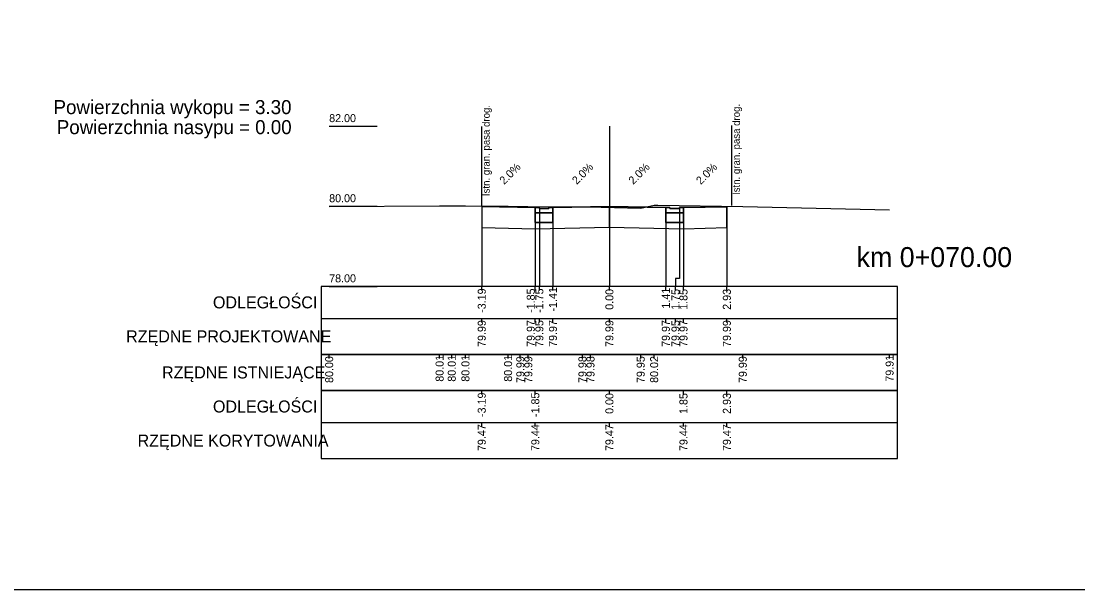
# Model space of a CAD drawing. Extents: x 7492871 to 7493499, y 5802964 to 5802992.
# Drawn here: x 7492903.18 to 7492929.58, y 5802963.88 to 5802978.08 of the extents above; entities that cross this region are included whole.
import ezdxf

# ---------------------------------------------------------------- set-up
doc = ezdxf.new("R2010")
doc.units = 0
for name, color, linetype in [('_wydruk', 7, 'Continuous'), ('d_pop_nasyp_opis', 7, 'Continuous'), ('d_pop_wykop_opis', 7, 'Continuous'), ('opisy_ramki_pop', 7, 'Continuous'), ('pop_comp_kostka', 7, 'Continuous'), ('pop_comp_lawa', 7, 'Continuous'), ('pop_comp_scieralna', 7, 'Continuous'), ('pop_granica_istn', 7, 'Continuous'), ('pop_opis', 7, 'Continuous'), ('pop_os', 7, 'Continuous'), ('pop_pikietaz', 7, 'Continuous'), ('pop_teren', 7, 'Continuous')]:
    doc.layers.add(name, color=color, linetype=linetype)

msp = doc.modelspace()

# ---------------------------------------------------------------- linework, layer by layer
msp.add_lwpolyline([(7492914.685, 5802973.452), (7492916.023, 5802973.425), (7492916.123, 5802973.425), (7492916.124, 5802973.405), (7492916.363, 5802973.405), (7492916.364, 5802973.425), (7492916.464, 5802973.425), (7492917.874, 5802973.453), (7492919.284, 5802973.425), (7492919.384, 5802973.425), (7492919.385, 5802973.405), (7492919.624, 5802973.405), (7492919.625, 5802973.425), (7492919.725, 5802973.425), (7492920.808, 5802973.447)])
at = {"layer": '_wydruk'}
msp.add_lwpolyline([(7492871.369, 5802992.281), (7493499.283, 5802992.281), (7493499.283, 5802963.881), (7492871.369, 5802963.881)], close=True, dxfattribs=at)
at = {"layer": 'opisy_ramki_pop'}
for points in [[(7492914.685, 5802972.932), (7492914.685, 5802971.659), (7492914.685, 5802971.659), (7492914.685, 5802971.459)], [(7492916.023, 5802972.896), (7492916.023, 5802971.659), (7492916.023, 5802971.659), (7492916.023, 5802971.459)], [(7492917.874, 5802972.933), (7492917.874, 5802971.659), (7492917.874, 5802971.659), (7492917.874, 5802971.459)], [(7492919.725, 5802972.896), (7492919.725, 5802971.659), (7492919.725, 5802971.659), (7492919.725, 5802971.459)], [(7492920.808, 5802972.927), (7492920.808, 5802971.659), (7492920.808, 5802971.659), (7492920.808, 5802971.459)]]:
    msp.add_lwpolyline(points, dxfattribs=at)
at = {"layer": 'pop_comp_kostka'}
for p, q in [((7492916.123, 5802973.425), (7492916.023, 5802973.425)), ((7492916.023, 5802973.425), (7492916.023, 5802973.295)), ((7492916.124, 5802973.405), (7492916.123, 5802973.425)), ((7492916.363, 5802973.405), (7492916.124, 5802973.405)), ((7492916.364, 5802973.425), (7492916.363, 5802973.405)), ((7492916.464, 5802973.425), (7492916.364, 5802973.425)), ((7492916.464, 5802973.295), (7492916.464, 5802973.425)), ((7492919.384, 5802973.425), (7492919.284, 5802973.425)), ((7492919.284, 5802973.425), (7492919.284, 5802973.295)), ((7492919.385, 5802973.405), (7492919.384, 5802973.425)), ((7492919.624, 5802973.405), (7492919.385, 5802973.405)), ((7492919.625, 5802973.425), (7492919.624, 5802973.405)), ((7492919.725, 5802973.425), (7492919.625, 5802973.425)), ((7492919.725, 5802973.295), (7492919.725, 5802973.425)), ((7492916.023, 5802973.295), (7492916.464, 5802973.295)), ((7492919.284, 5802973.295), (7492919.725, 5802973.295))]:
    msp.add_line(p, q, dxfattribs=at)
at = {"layer": 'pop_comp_lawa'}
for p, q in [((7492916.464, 5802973.295), (7492916.023, 5802973.295)), ((7492916.023, 5802973.295), (7492916.023, 5802973.055)), ((7492916.464, 5802973.055), (7492916.464, 5802973.295)), ((7492919.725, 5802973.295), (7492919.284, 5802973.295)), ((7492919.284, 5802973.295), (7492919.284, 5802973.055)), ((7492919.725, 5802973.055), (7492919.725, 5802973.295)), ((7492916.023, 5802973.055), (7492916.464, 5802973.055)), ((7492919.284, 5802973.055), (7492919.725, 5802973.055))]:
    msp.add_line(p, q, dxfattribs=at)
at = {"layer": 'pop_comp_scieralna'}
for p, q in [((7492916.023, 5802973.425), (7492914.685, 5802973.452)), ((7492914.685, 5802973.452), (7492914.685, 5802972.932)), ((7492916.023, 5802973.055), (7492916.023, 5802973.425)), ((7492917.874, 5802973.453), (7492916.464, 5802973.425)), ((7492916.464, 5802973.425), (7492916.464, 5802973.055)), ((7492917.874, 5802972.933), (7492917.874, 5802973.453)), ((7492919.284, 5802973.425), (7492917.874, 5802973.453)), ((7492917.874, 5802973.453), (7492917.874, 5802972.933)), ((7492919.284, 5802973.055), (7492919.284, 5802973.425)), ((7492920.808, 5802973.447), (7492919.725, 5802973.425)), ((7492919.725, 5802973.425), (7492919.725, 5802973.055)), ((7492920.808, 5802972.927), (7492920.808, 5802973.447)), ((7492914.685, 5802972.932), (7492916.023, 5802972.896)), ((7492916.464, 5802973.055), (7492916.023, 5802973.055)), ((7492916.023, 5802972.896), (7492917.874, 5802972.933)), ((7492917.874, 5802972.933), (7492919.725, 5802972.896)), ((7492919.725, 5802973.055), (7492919.284, 5802973.055)), ((7492919.725, 5802972.896), (7492920.808, 5802972.927))]:
    msp.add_line(p, q, dxfattribs=at)
at = {"layer": 'pop_granica_istn'}
for p, q in [((7492920.934, 5802973.979), (7492920.934, 5802975.479)), ((7492914.685, 5802973.952), (7492914.685, 5802975.452)), ((7492914.685, 5802973.452), (7492914.685, 5802973.952)), ((7492920.934, 5802973.479), (7492920.934, 5802973.979))]:
    msp.add_line(p, q, dxfattribs=at)
at = {"layer": 'pop_opis'}
for p, q in [((7492910.874, 5802975.459), (7492912.074, 5802975.459)), ((7492910.874, 5802973.459), (7492912.074, 5802973.459)), ((7492910.674, 5802971.459), (7492910.674, 5802969.759)), ((7492910.674, 5802971.459), (7492910.674, 5802969.759)), ((7492910.674, 5802971.459), (7492910.674, 5802969.759)), ((7492910.674, 5802971.459), (7492910.674, 5802969.759)), ((7492910.874, 5802971.459), (7492912.074, 5802971.459)), ((7492914.685, 5802971.359), (7492914.685, 5802971.459)), ((7492916.023, 5802971.359), (7492916.023, 5802971.459)), ((7492916.124, 5802971.359), (7492916.124, 5802971.459)), ((7492916.464, 5802971.359), (7492916.464, 5802971.459)), ((7492917.874, 5802971.359), (7492917.874, 5802971.459)), ((7492919.284, 5802971.359), (7492919.284, 5802971.459)), ((7492919.525, 5802971.359), (7492919.525, 5802971.459)), ((7492919.725, 5802971.359), (7492919.725, 5802971.459)), ((7492920.808, 5802971.359), (7492920.808, 5802971.459)), ((7492910.674, 5802970.659), (7492925.074, 5802970.659)), ((7492910.674, 5802970.659), (7492925.074, 5802970.659)), ((7492910.674, 5802970.659), (7492925.074, 5802970.659)), ((7492910.674, 5802970.659), (7492925.074, 5802970.659)), ((7492914.685, 5802970.559), (7492914.685, 5802970.659)), ((7492916.023, 5802970.559), (7492916.023, 5802970.659)), ((7492916.124, 5802970.559), (7492916.124, 5802970.659)), ((7492916.464, 5802970.559), (7492916.464, 5802970.659)), ((7492917.874, 5802970.559), (7492917.874, 5802970.659)), ((7492919.284, 5802970.559), (7492919.284, 5802970.659)), ((7492919.525, 5802970.559), (7492919.525, 5802970.659)), ((7492919.725, 5802970.559), (7492919.725, 5802970.659)), ((7492920.808, 5802970.559), (7492920.808, 5802970.659)), ((7492910.674, 5802969.759), (7492910.674, 5802968.859)), ((7492910.874, 5802969.659), (7492910.874, 5802969.759)), ((7492913.632, 5802969.659), (7492913.632, 5802969.759)), ((7492913.936, 5802969.659), (7492913.936, 5802969.759)), ((7492914.278, 5802969.659), (7492914.278, 5802969.759)), ((7492915.343, 5802969.659), (7492915.343, 5802969.759)), ((7492915.649, 5802969.659), (7492915.649, 5802969.759)), ((7492915.849, 5802969.659), (7492915.849, 5802969.759)), ((7492917.202, 5802969.659), (7492917.202, 5802969.759)), ((7492917.402, 5802969.659), (7492917.402, 5802969.759)), ((7492918.656, 5802969.659), (7492918.656, 5802969.759)), ((7492918.992, 5802969.659), (7492918.992, 5802969.759)), ((7492921.206, 5802969.659), (7492921.206, 5802969.759)), ((7492924.874, 5802969.659), (7492924.874, 5802969.759)), ((7492910.674, 5802968.859), (7492910.674, 5802967.159)), ((7492914.685, 5802968.759), (7492914.685, 5802968.859)), ((7492916.023, 5802968.759), (7492916.023, 5802968.859)), ((7492917.874, 5802968.759), (7492917.874, 5802968.859)), ((7492919.725, 5802968.759), (7492919.725, 5802968.859)), ((7492920.808, 5802968.759), (7492920.808, 5802968.859)), ((7492910.674, 5802968.059), (7492925.074, 5802968.059)), ((7492914.685, 5802967.959), (7492914.685, 5802968.059)), ((7492916.023, 5802967.959), (7492916.023, 5802968.059)), ((7492917.874, 5802967.959), (7492917.874, 5802968.059)), ((7492919.725, 5802967.959), (7492919.725, 5802968.059)), ((7492920.808, 5802967.959), (7492920.808, 5802968.059))]:
    msp.add_line(p, q, dxfattribs=at)
for points in [[(7492914.685, 5802973.452), (7492914.685, 5802971.659), (7492914.685, 5802971.659), (7492914.685, 5802971.459)], [(7492916.023, 5802973.425), (7492916.023, 5802971.659), (7492916.023, 5802971.659), (7492916.023, 5802971.459)], [(7492916.124, 5802973.405), (7492916.124, 5802971.659), (7492916.124, 5802971.659), (7492916.124, 5802971.459)], [(7492916.464, 5802973.425), (7492916.464, 5802971.659), (7492916.464, 5802971.659), (7492916.464, 5802971.459)], [(7492917.874, 5802973.453), (7492917.874, 5802971.659), (7492917.874, 5802971.659), (7492917.874, 5802971.459)], [(7492919.284, 5802973.425), (7492919.284, 5802971.659), (7492919.284, 5802971.659), (7492919.284, 5802971.459)], [(7492919.624, 5802973.405), (7492919.624, 5802971.659), (7492919.525, 5802971.659), (7492919.525, 5802971.459)], [(7492919.725, 5802973.425), (7492919.725, 5802971.659), (7492919.725, 5802971.659), (7492919.725, 5802971.459)], [(7492920.808, 5802973.447), (7492920.808, 5802971.659), (7492920.808, 5802971.659), (7492920.808, 5802971.459)]]:
    msp.add_lwpolyline(points, dxfattribs=at)
for points in [[(7492910.674, 5802971.459), (7492910.674, 5802969.759), (7492925.074, 5802969.759), (7492925.074, 5802971.459)], [(7492910.674, 5802971.459), (7492910.674, 5802969.759), (7492925.074, 5802969.759), (7492925.074, 5802971.459)], [(7492910.674, 5802971.459), (7492910.674, 5802969.759), (7492925.074, 5802969.759), (7492925.074, 5802971.459)], [(7492910.674, 5802971.459), (7492910.674, 5802969.759), (7492925.074, 5802969.759), (7492925.074, 5802971.459)], [(7492910.674, 5802969.759), (7492910.674, 5802968.859), (7492925.074, 5802968.859), (7492925.074, 5802969.759)], [(7492910.674, 5802968.859), (7492910.674, 5802967.159), (7492925.074, 5802967.159), (7492925.074, 5802968.859)]]:
    msp.add_lwpolyline(points, close=True, dxfattribs=at)
at = {"layer": 'pop_os'}
msp.add_line((7492917.874, 5802975.459), (7492917.874, 5802971.459), dxfattribs=at)
at = {"layer": 'pop_teren'}
msp.add_lwpolyline([(7492910.874, 5802973.455), (7492913.632, 5802973.472), (7492913.936, 5802973.473), (7492914.278, 5802973.467), (7492915.343, 5802973.465), (7492915.649, 5802973.449), (7492915.84, 5802973.454), (7492917.202, 5802973.443), (7492917.332, 5802973.444), (7492918.656, 5802973.412), (7492918.992, 5802973.483), (7492919.085, 5802973.485), (7492921.206, 5802973.451), (7492924.874, 5802973.371)], dxfattribs=at)

# ---------------------------------------------------------------- texts
at = {"layer": 'd_pop_nasyp_opis'}
msp.add_text('Powierzchnia nasypu = 0.00', height=0.35, dxfattribs=at).set_placement((7492904.069, 5802975.259))
at = {"layer": 'd_pop_wykop_opis'}
msp.add_text('Powierzchnia wykopu = 3.30', height=0.35, dxfattribs=at).set_placement((7492903.988, 5802975.759))
at = {"layer": 'pop_granica_istn'}
for p in [(7492921.133, 5802973.74), (7492914.884, 5802973.713)]:
    msp.add_text('Istn. gran. pasa drog.', height=0.18, rotation=90, dxfattribs=at).set_placement(p)
at = {"layer": 'pop_opis'}
for s, height, p in [('82.00', 0.2, (7492910.874, 5802975.559)), ('80.00', 0.2, (7492910.874, 5802973.559)), ('78.00', 0.2, (7492910.874, 5802971.559)), ('ODLEGŁOŚCI', 0.3, (7492907.97, 5802970.909)), ('ODLEGŁOŚCI', 0.3, (7492907.97, 5802970.909)), ('ODLEGŁOŚCI', 0.3, (7492907.97, 5802970.909)), ('ODLEGŁOŚCI', 0.3, (7492907.97, 5802970.909)), ('RZĘDNE PROJEKTOWANE', 0.3, (7492905.802, 5802970.059)), ('RZĘDNE PROJEKTOWANE', 0.3, (7492905.802, 5802970.059)), ('RZĘDNE PROJEKTOWANE', 0.3, (7492905.802, 5802970.059)), ('RZĘDNE PROJEKTOWANE', 0.3, (7492905.802, 5802970.059)), ('RZĘDNE ISTNIEJĄCE', 0.3, (7492906.699, 5802969.159)), ('ODLEGŁOŚCI', 0.3, (7492907.97, 5802968.309)), ('RZĘDNE KORYTOWANIA', 0.3, (7492906.088, 5802967.459))]:
    msp.add_text(s, height=height, dxfattribs=at).set_placement(p)
for s, rotation, p in [('2.0%', 45, (7492915.246, 5802973.988)), ('2.0%', 45, (7492917.06, 5802973.989)), ('2.0%', 45, (7492918.47, 5802973.989)), ('2.0%', 45, (7492920.158, 5802973.986)), ('-3.19', 90, (7492914.785, 5802970.797)), ('-1.85', 90, (7492916.01, 5802970.796)), ('-1.75', 90, (7492916.224, 5802970.796)), ('-1.41', 90, (7492916.564, 5802970.829)), ('0.00', 90, (7492917.974, 5802970.874)), ('1.41', 90, (7492919.384, 5802970.905)), ('1.75', 90, (7492919.625, 5802970.873)), ('1.85', 90, (7492919.825, 5802970.873)), ('2.93', 90, (7492920.908, 5802970.874)), ('79.99', 90, (7492914.785, 5802969.946)), ('79.97', 90, (7492916.01, 5802969.947)), ('79.95', 90, (7492916.224, 5802969.945)), ('79.97', 90, (7492916.564, 5802969.947)), ('79.99', 90, (7492917.974, 5802969.946)), ('79.97', 90, (7492919.384, 5802969.947)), ('79.95', 90, (7492919.625, 5802969.945)), ('79.97', 90, (7492919.825, 5802969.947)), ('79.99', 90, (7492920.908, 5802969.946)), ('80.00', 90, (7492910.974, 5802969.047)), ('80.01', 90, (7492913.732, 5802969.078)), ('80.01', 90, (7492914.036, 5802969.078)), ('80.01', 90, (7492914.378, 5802969.078)), ('80.01', 90, (7492915.443, 5802969.078)), ('79.99', 90, (7492915.749, 5802969.046)), ('79.99', 90, (7492915.949, 5802969.046)), ('79.98', 90, (7492917.302, 5802969.046)), ('79.98', 90, (7492917.502, 5802969.046)), ('79.95', 90, (7492918.756, 5802969.045)), ('80.02', 90, (7492919.092, 5802969.048)), ('79.99', 90, (7492921.306, 5802969.046)), ('79.91', 90, (7492924.974, 5802969.078)), ('-3.19', 90, (7492914.785, 5802968.197)), ('-1.85', 90, (7492916.123, 5802968.196)), ('0.00', 90, (7492917.974, 5802968.274)), ('1.85', 90, (7492919.825, 5802968.273)), ('2.93', 90, (7492920.908, 5802968.274)), ('79.47', 90, (7492914.785, 5802967.347)), ('79.44', 90, (7492916.123, 5802967.347)), ('79.47', 90, (7492917.974, 5802967.347)), ('79.44', 90, (7492919.825, 5802967.347)), ('79.47', 90, (7492920.908, 5802967.347))]:
    msp.add_text(s, height=0.2, rotation=rotation, dxfattribs=at).set_placement(p)
at = {"layer": 'pop_pikietaz'}
msp.add_text('km 0+070.00', height=0.5, dxfattribs=at).set_placement((7492924.05, 5802971.939))

doc.saveas('drawing.dxf')
